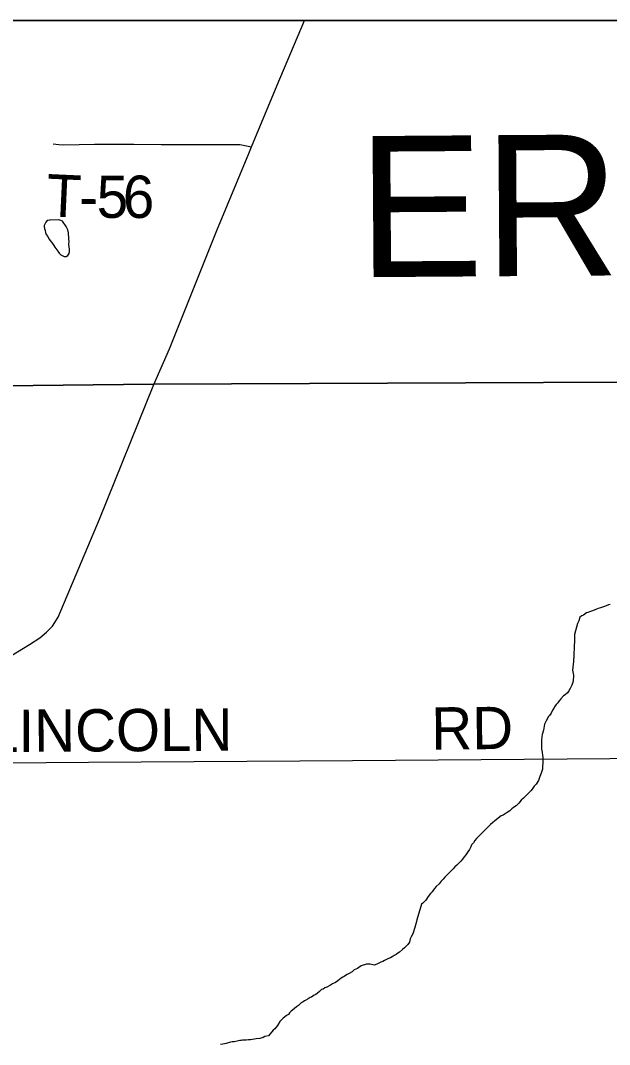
# Model space of a CAD drawing. Extents: x 0 to 34, y 0 to 22.
# Drawn here: x 4.825 to 5.615, y 19.525 to 20.9 of the extents above; entities that cross this region are included whole.
import ezdxf

# ---------------------------------------------------------------- set-up
doc = ezdxf.new("R2010")
doc.units = 0
for name, color, linetype in [('GM_X_Corporation', 7, 'Continuous'), ('GM_X_County_Text', 7, 'Continuous'), ('GM_X_Minor_Lake', 7, 'Continuous'), ('GM_X_Minor_River', 7, 'Continuous'), ('GM_X_State_Route', 7, 'Continuous'), ('GM_X_Township_Road', 7, 'Continuous'), ('GM_X_Township_Road_Text', 7, 'Continuous'), ('SH_Data', 7, 'Continuous')]:
    doc.layers.add(name, color=color, linetype=linetype)

msp = doc.modelspace()

# ---------------------------------------------------------------- linework, layer by layer
at = {"layer": 'GM_X_Corporation'}
for points in [[(6.9799, 20.9), (2.1, 20.9)], [(6.9799, 20.9), (2.1, 20.9)], [(5.9453, 20.4158), (5.0033, 20.4116), (4.0334, 20.4012), (3.3271, 20.397)], [(3.3271, 20.397), (4.0334, 20.4012), (5.0033, 20.4116), (5.9453, 20.4158)], [(5.9453, 20.4158), (5.0033, 20.4116), (4.0334, 20.4012), (3.3271, 20.397)], [(3.3271, 20.397), (4.0334, 20.4012), (5.0033, 20.4116), (5.9453, 20.4158)]]:
    msp.add_lwpolyline(points, dxfattribs=at)
at = {"layer": 'GM_X_Minor_Lake'}
for points in [[(4.8644, 20.6321), (4.8636, 20.6321), (4.8606, 20.6313), (4.8587, 20.6294), (4.8572, 20.6267), (4.8565, 20.6248), (4.8565, 20.6229), (4.8569, 20.6206), (4.8577, 20.6179), (4.8581, 20.6153), (4.8593, 20.6126), (4.8612, 20.61), (4.8627, 20.607)], [(4.8627, 20.607), (4.8674, 20.6005), (4.8693, 20.5979), (4.8708, 20.5956), (4.8747, 20.5903), (4.8766, 20.5877), (4.8789, 20.5854), (4.8816, 20.5839), (4.8835, 20.5832), (4.8858, 20.5832), (4.8881, 20.5844), (4.8899, 20.5871), (4.8903, 20.5894), (4.8903, 20.5913), (4.8903, 20.5932), (4.8898, 20.5962), (4.8894, 20.5992), (4.8898, 20.6038), (4.8897, 20.6061), (4.8897, 20.6095), (4.8893, 20.6126), (4.8889, 20.6148), (4.8881, 20.619), (4.8873, 20.6209), (4.8861, 20.6236), (4.8842, 20.6262), (4.8827, 20.6281), (4.8811, 20.6304), (4.8788, 20.6315), (4.8762, 20.6322), (4.8644, 20.6321)]]:
    msp.add_lwpolyline(points, dxfattribs=at)
at = {"layer": 'GM_X_Minor_River'}
for points in [[(5.6159, 20.116), (5.6136, 20.1153), (5.6105, 20.1142), (5.6071, 20.113), (5.6029, 20.1115), (5.5999, 20.1108), (5.5976, 20.1097), (5.5945, 20.1082), (5.5911, 20.107), (5.5884, 20.1059), (5.5861, 20.1052), (5.5842, 20.1048), (5.5804, 20.1018), (5.5781, 20.1006), (5.5754, 20.0988), (5.5739, 20.0938), (5.572, 20.0904), (5.5681, 20.0756), (5.5681, 20.0714), (5.5681, 20.0653), (5.5677, 20.0612), (5.5676, 20.0566), (5.5672, 20.0509), (5.5672, 20.0479), (5.5668, 20.0395), (5.566, 20.0319), (5.5656, 20.0277), (5.5667, 20.0209), (5.5663, 20.0129), (5.5644, 20.0076), (5.5624, 20.0034), (5.5605, 20), (5.5586, 19.9974), (5.5555, 19.9947), (5.5532, 19.9932), (5.5498, 19.9894), (5.5475, 19.9868), (5.5456, 19.9841), (5.5437, 19.9815), (5.5414, 19.9784), (5.5402, 19.9765), (5.5387, 19.9743), (5.5368, 19.9701), (5.5345, 19.9671), (5.5329, 19.9652), (5.5318, 19.9629), (5.5303, 19.9599), (5.5287, 19.9572), (5.528, 19.9553), (5.5264, 19.9473), (5.5248, 19.9413), (5.5241, 19.9386), (5.524, 19.9333), (5.524, 19.928), (5.524, 19.9242), (5.524, 19.9219)], [(5.524, 19.9219), (5.5247, 19.9177), (5.5251, 19.9131), (5.5258, 19.9109), (5.5258, 19.9086), (5.5258, 19.9025), (5.5254, 19.8995), (5.5254, 19.8972), (5.525, 19.8949), (5.5242, 19.8922), (5.5235, 19.8896), (5.5227, 19.8873), (5.5215, 19.885), (5.52, 19.8797), (5.5169, 19.8748), (5.5142, 19.8721), (5.5123, 19.8695), (5.51, 19.8661), (5.5062, 19.8627), (5.5028, 19.8593), (5.4997, 19.8559), (5.4966, 19.8532), (5.4936, 19.8494), (5.4898, 19.8457), (5.4863, 19.8434), (5.484, 19.8415), (5.4814, 19.8389), (5.4779, 19.8366), (5.4749, 19.8347), (5.4726, 19.8332), (5.4699, 19.8321), (5.4611, 19.8257), (5.4581, 19.823), (5.4554, 19.8207), (5.4531, 19.8185), (5.4504, 19.8158), (5.4477, 19.8132), (5.4455, 19.8109), (5.4432, 19.8086), (5.4405, 19.806), (5.4382, 19.8037), (5.4367, 19.8018), (5.4344, 19.7992), (5.4324, 19.7958), (5.4301, 19.7931), (5.429, 19.7908), (5.4271, 19.7871), (5.4248, 19.784), (5.4221, 19.7799), (5.4202, 19.7772), (5.4179, 19.7742), (5.4156, 19.7715), (5.4129, 19.7685), (5.4102, 19.7659), (5.4076, 19.7636), (5.4053, 19.7613), (5.4033, 19.7594), (5.4011, 19.7572), (5.3988, 19.7545), (5.3961, 19.7519), (5.3942, 19.75), (5.3919, 19.7473), (5.3892, 19.7447), (5.3865, 19.7409), (5.3827, 19.7375), (5.3804, 19.7348), (5.3789, 19.7329), (5.377, 19.7303), (5.3747, 19.728), (5.3716, 19.7239), (5.3685, 19.7189), (5.3647, 19.7148), (5.3628, 19.7136), (5.3566, 19.6924), (5.3562, 19.6905), (5.3539, 19.6821), (5.3512, 19.6738), (5.3489, 19.6696), (5.3477, 19.667), (5.3466, 19.6628), (5.3446, 19.6597), (5.3424, 19.6571), (5.3401, 19.6548), (5.3374, 19.6526), (5.3332, 19.6492), (5.3309, 19.6477), (5.3286, 19.6461), (5.3263, 19.6446), (5.3236, 19.6431), (5.3214, 19.6416), (5.3187, 19.6405), (5.316, 19.6394), (5.3133, 19.6379), (5.3107, 19.6367), (5.3084, 19.636), (5.3057, 19.6345), (5.3027, 19.6333), (5.2992, 19.6318), (5.294, 19.6331)], [(5.294, 19.6331), (5.2888, 19.6331), (5.2865, 19.6323), (5.2846, 19.6319), (5.2819, 19.6308), (5.2789, 19.6285), (5.277, 19.6274), (5.2747, 19.6262), (5.2724, 19.6255), (5.2697, 19.6228), (5.2659, 19.6205), (5.2629, 19.619), (5.261, 19.6179), (5.2591, 19.6167), (5.2572, 19.6156), (5.2549, 19.6145), (5.2507, 19.6107), (5.2473, 19.6084), (5.2435, 19.6069), (5.2405, 19.605), (5.2359, 19.6023), (5.2332, 19.6012), (5.231, 19.5996), (5.2287, 19.5989), (5.226, 19.5966), (5.223, 19.5939), (5.2211, 19.5924), (5.2188, 19.5913), (5.2154, 19.589), (5.2135, 19.5883), (5.2108, 19.5867), (5.2078, 19.5848), (5.2059, 19.5837), (5.204, 19.5826), (5.2013, 19.581), (5.1979, 19.5776), (5.1952, 19.5757), (5.1926, 19.5734), (5.1899, 19.5712), (5.188, 19.57), (5.1857, 19.5677), (5.1842, 19.5655), (5.1815, 19.5643), (5.1789, 19.562), (5.177, 19.5605), (5.1747, 19.5579), (5.1728, 19.556), (5.1697, 19.5506), (5.1659, 19.5461), (5.1636, 19.5446), (5.1576, 19.537), (5.1526, 19.5358), (5.1503, 19.5347), (5.1458, 19.5335), (5.1408, 19.5328), (5.1386, 19.5324), (5.1355, 19.532), (5.1332, 19.5313), (5.1306, 19.5313), (5.1275, 19.5309), (5.1249, 19.5309), (5.1226, 19.5309), (5.1207, 19.5305), (5.1188, 19.5305), (5.1154, 19.5298), (5.1131, 19.5294), (5.1112, 19.529), (5.1089, 19.5286), (5.1063, 19.5282), (5.1006, 19.5264), (5.096, 19.5256), (5.093, 19.5252)]]:
    msp.add_lwpolyline(points, dxfattribs=at)
at = {"layer": 'GM_X_State_Route'}
for points in [[(5.0036, 20.4111), (5.0246, 20.4592), (5.0883, 20.6179), (5.1309, 20.7215), (5.1345, 20.7303), (5.1692, 20.8133), (5.2057, 20.9)], [(4.7556, 20.0128), (4.8366, 20.0623), (4.8506, 20.0713), (4.8594, 20.0786), (4.8675, 20.0869), (4.8751, 20.0989), (4.9306, 20.2303), (5.0036, 20.4111)]]:
    msp.add_lwpolyline(points, dxfattribs=at)
at = {"layer": 'GM_X_Township_Road'}
for points in [[(4.8683, 20.7343), (4.8761, 20.7335), (4.8829, 20.7332), (4.9239, 20.734), (4.9768, 20.734), (5.0134, 20.7337), (5.0377, 20.7335), (5.0607, 20.7333), (5.0893, 20.7335), (5.1135, 20.7337), (5.119, 20.7335), (5.1219, 20.7332), (5.1258, 20.7323), (5.1302, 20.7313), (5.1345, 20.7303)], [(4.5747, 19.9017), (4.9161, 19.9044), (5.2701, 19.9067), (5.6733, 19.9097), (5.9557, 19.9128), (6.1689, 19.9144), (6.598, 19.9189), (6.9991, 19.9206)]]:
    msp.add_lwpolyline(points, dxfattribs=at)
at = {"layer": 'SH_Data'}
msp.add_line((2.1, 20.9), (8.9, 20.9), dxfattribs=at)

# ---------------------------------------------------------------- texts
at = {"layer": 'GM_X_County_Text'}
msp.add_text('ERIE COUNTY', height=0.189394, rotation=0.4039, dxfattribs=at).set_placement((5.2777, 20.5553))
at = {"layer": 'GM_X_Township_Road_Text'}
for s, height, rotation, p in [('T', 0.0568, 357.3593, (4.8584, 20.6372)), ('5', 0.0568, 359.8912, (4.9269, 20.635)), ('6', 0.0568, 359.9932, (4.962, 20.6349)), ('-', 0.0568, 359.5975, (4.9033, 20.6351)), ('LINCOLN', 0.05682, 0.3124, (4.7798, 19.9178)), ('RD', 0.05682, 0.4937, (5.3762, 19.9211))]:
    msp.add_text(s, height=height, rotation=rotation, dxfattribs=at).set_placement(p)

doc.saveas('drawing.dxf')
